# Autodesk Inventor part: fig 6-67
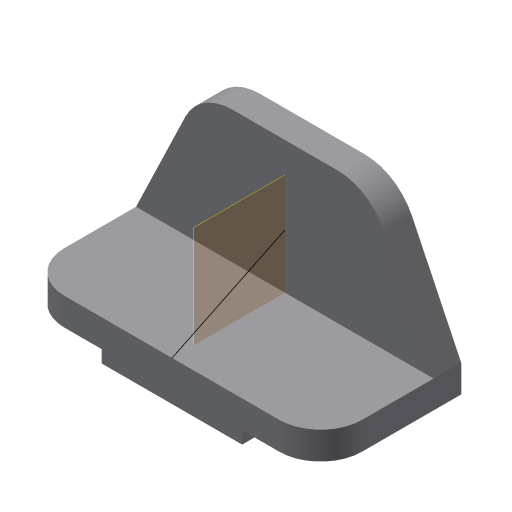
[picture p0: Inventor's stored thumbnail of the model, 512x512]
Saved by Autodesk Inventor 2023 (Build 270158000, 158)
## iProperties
Created: 2001-12
Part Number: fig 6-67
Document SubType Name: Modeling
Designer: Renu Muthoo
Density: 1 g/cm^3
Material: Generic
Appearance: Default
Control State: 0
Master: False
Checked Out: False
Shininess: 77.0
Length Units: 11269
Angle Units: 11279
Time Units: 11290
Mass Units: 11283
Length Display Precision: 3
Angle Display Precision: 2
Density: 0.0
Volumn: 0.0
Area: 0.0
PropertySet Name: Model Information
Author: Renu Muthoo
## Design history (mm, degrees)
node "Sketch1"
sketch "Sketch2"
  geometry: L1 (-67.219, 19.116)-(148.781, 19.116); L2 (148.781, 19.116)-(148.781, -0.884); L3 (-67.219, -0.884)-(-67.219, 19.116); L4 (-10.219, -0.884)-(-10.219, -9.884); L5 (-10.219, -9.884)-(91.781, -9.884); L6 (91.781, -9.884)-(91.781, -0.884); L7 (148.781, -0.884)-(91.781, -0.884); L8 (-10.219, -0.884)-(-67.219, -0.884)
  constraints: 16 end point, 5 parallel, 4 perpendicular, 2 equal length, 1 horizontal
  dimensions: "d0" = 102 distance of L4.end L5.end; "d1" = 57 distance of L4.start L3.start; "d2" = 29 distance between parallel lines of L1 L5; "d3" = 20 distance of L1.end L2.end
extrude "Extrusion1" new body sketch "Sketch2" distance "d4" = 102; taper "d5" = 0 deg
sketch "Sketch3"
  geometry: L1 (67.219, -19.116)-(-148.781, -19.116) reference; L2 (67.219, -19.116)-(31.475, -93.564); L3 (-2.781, -115.116)-(-78.781, -115.116); L4 (-113.038, -93.564)-(-148.781, -19.116); A1 r 38 centre (-2.781, -77.116) between (-2.781, -115.116) and (31.475, -93.564); A2 r 38 centre (-78.781, -77.116) between (-113.038, -93.564) and (-78.781, -115.116)
  constraints: 6 end point, 4 point on circle, 4 tangent, 2 centre point, 1 equal length, 1 equal radius, 1 parallel
  dimensions: "d6" = 96 distance between parallel lines of L3 L1; "d7" = 38 radius of A1; "d8" = 76 distance of A2.centre A1.centre
extrude "Extrusion2" join sketch "Sketch3" distance "d9" = 20; taper "d10" = 0 deg
fillet "Fillet1" dims "d11" = 30
workplane "Work Plane1"
sketch "Sketch7"
  geometry: L1 (0, -82)-(-39.557, 0)
  constraints: 2 end point
body "Solid1"
other parameters: "d12" = -108
